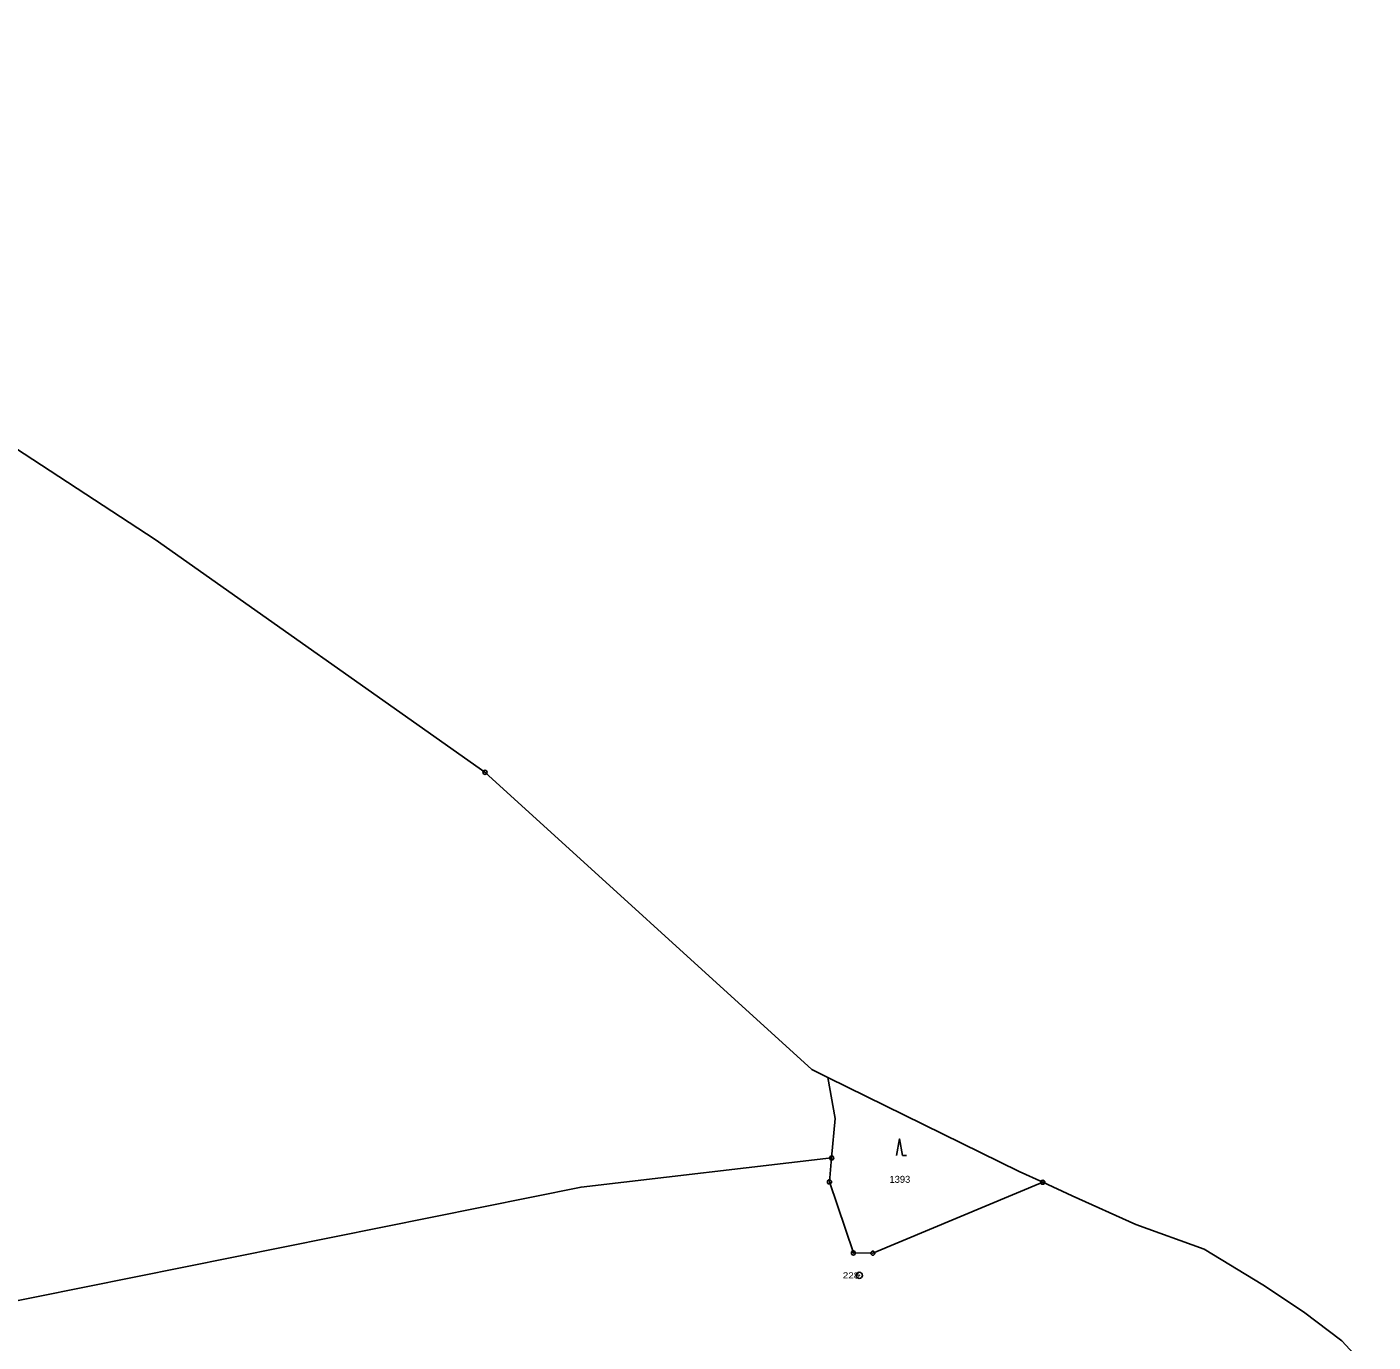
# Model space of a CAD drawing. Extents: x -872229 to -869198, y -1075981 to -1074329.
# Drawn here: x -870040 to -869712.8, y -1074649.5 to -1074330 of the extents above; entities that cross this region are included whole.
import ezdxf
from ezdxf.enums import TextEntityAlignment as Align

# ---------------------------------------------------------------- set-up
doc = ezdxf.new("R2010")
doc.units = 0
doc.header["$LTSCALE"] = 0.68
for name, color, linetype, lineweight in [('1', 7, 'Continuous', 25), ('3', 7, 'Continuous', 25), ('8', 7, 'Continuous', 25)]:
    doc.layers.add(name, color=color, linetype=linetype, lineweight=lineweight)
doc.layers.add('2', color=7, linetype='Continuous')

msp = doc.modelspace()

# ---------------------------------------------------------------- linework, layer by layer
at = {"layer": '1'}
for points in [[(-869845.36, -1074585.19), (-869849.22, -1074583.29), (-869928.7, -1074511.08), (-870008.87, -1074454.49), (-870089.47, -1074401.85), (-870105.39, -1074390.59), (-870125.42, -1074373.82), (-870146.26, -1074356.79), (-870155.38, -1074350), (-870173.37, -1074331.09), (-870189.91, -1074330), (-870230.75, -1074347.75)], [(-869793.12, -1074610.67), (-869798.86, -1074608.03), (-869845.36, -1074585.19)], [(-869845.36, -1074585.19), (-869843.57, -1074595.19), (-869844.44, -1074604.77)], [(-869844.44, -1074604.77), (-869905.34, -1074611.83), (-870062.32, -1074643.41)], [(-869793.12, -1074610.67), (-869834.42, -1074627.89), (-869839.15, -1074627.85), (-869844.97, -1074610.58), (-869844.44, -1074604.77)], [(-869712.84, -1074657.47), (-869720.42, -1074649.17), (-869729.76, -1074642.12), (-869739.64, -1074635.61), (-869753.88, -1074626.92), (-869770.54, -1074620.9), (-869785.96, -1074613.96), (-869793.12, -1074610.67)]]:
    msp.add_lwpolyline(points, dxfattribs=at)
at = {"layer": '3'}
msp.add_line((-869827.21, -1074604.15), (-869826.214, -1074604.15), dxfattribs=at)
msp.add_lwpolyline([(-869827.21, -1074604.15), (-869827.96, -1074600.15), (-869828.71, -1074604.15)], dxfattribs=at)
at = {"layer": '8'}
for centre, radius in [((-869928.7, -1074511.0799), 0.5), ((-869928.7, -1074511.0799), 0.0303), ((-869844.44, -1074604.7699), 0.5), ((-869844.44, -1074604.7699), 0.0303), ((-869844.97, -1074610.5799), 0.5), ((-869844.97, -1074610.5799), 0.0303), ((-869793.12, -1074610.6699), 0.5), ((-869793.12, -1074610.6699), 0.0303), ((-869839.15, -1074627.8499), 0.5), ((-869834.42, -1074627.8899), 0.5), ((-869839.15, -1074627.8499), 0.0303), ((-869834.42, -1074627.8899), 0.0303), ((-869837.72, -1074633.2898), 0.75), ((-869837.72, -1074633.2898), 0.03)]:
    msp.add_circle(centre, radius, dxfattribs=at)

# ---------------------------------------------------------------- texts
at = {"layer": '2'}
msp.add_text('1393', height=1.7, dxfattribs=at).set_placement((-869830.38, -1074610.81))
at = {"layer": '8', "width": 1.2}
msp.add_text('228', height=1.5, dxfattribs=at).set_placement((-869837.72, -1074634.04), align=Align.RIGHT)

doc.saveas('drawing.dxf')
